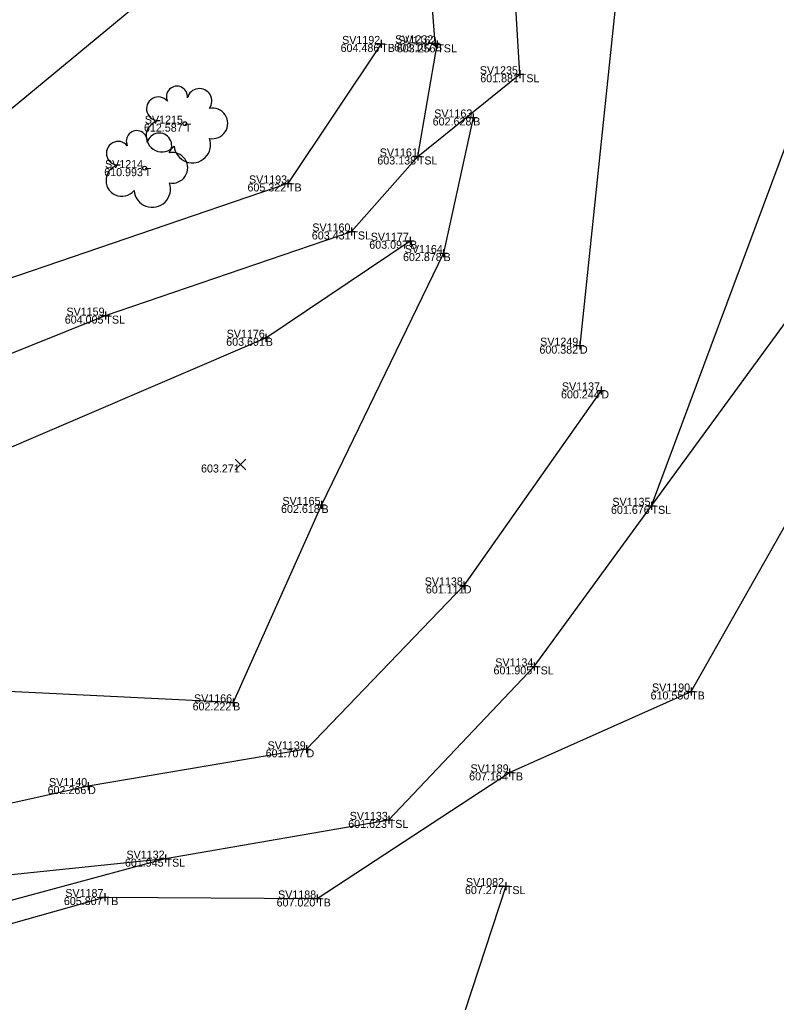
# Model space of a CAD drawing. Extents: x -2 to 1979875, y -2 to 232027.
# Drawn here: x 1978852.3 to 1978899.5, y 231261.4 to 231322.8 of the extents above; entities that cross this region are included whole.
import ezdxf

# ---------------------------------------------------------------- set-up
doc = ezdxf.new("R2010")
doc.units = 0
for name, color, linetype in [('_CIVIL_CONSTRUCTION', 7, 'Continuous'), ('DR_X_Ditch', 7, 'Continuous'), ('GE_P_Alignment', 7, 'Continuous'), ('GE_X_Alignment', 7, 'Continuous'), ('GE_X_Alignment_100_Curve_Data', 7, 'Continuous'), ('GE_X_Alignment_100_Stations', 7, 'Continuous'), ('HY_X_Water_Edge', 7, 'Continuous'), ('SV_X_Random_Point', 7, 'Continuous'), ('SV_X_Toe_of_Slope', 7, 'Continuous'), ('SV_X_Top_of_Bank', 7, 'Continuous'), ('VG_X_Cells', 7, 'Continuous')]:
    doc.layers.add(name, color=color, linetype=linetype)

msp = doc.modelspace()

# ---------------------------------------------------------------- linework, layer by layer
at = {"layer": 'DR_X_Ditch'}
for points in [[(1978869.602, 231440.78), (1978870, 231423.312), (1978870.757, 231401.498), (1978878.811, 231381.318), (1978885.453, 231363.805), (1978889.017, 231343.317), (1978889.726, 231326.131), (1978887.247, 231302.424)], [(1978888.584, 231299.627), (1978879.993, 231287.447), (1978870.172, 231277.213), (1978856.534, 231274.917), (1978839.012, 231271.025), (1978823.007, 231263.425), (1978802.617, 231258.705), (1978787.259, 231269.564)]]:
    msp.add_lwpolyline(points, dxfattribs=at)
at = {"layer": 'GE_P_Alignment'}
for points in [[(1978878.198, 231321.306), (1978876.972, 231337.361), (1978875.092, 231351.7)], [(1978823.841, 231302.538), (1978835.598, 231310.121), (1978846.229, 231312.385), (1978850.512, 231316.224), (1978859.326, 231323.503), (1978863.746, 231327.737), (1978864.641, 231332.322)], [(1978880.582, 231316.673), (1978878.73, 231308.205), (1978871.111, 231292.475), (1978865.586, 231280.144), (1978848.135, 231280.988), (1978836.093, 231277.946), (1978823.874, 231270.699), (1978811.412, 231263.896), (1978801.351, 231263.66), (1978797.393, 231268.655), (1978813.97, 231278.694), (1978829.592, 231287.989), (1978849.277, 231295.052), (1978867.627, 231302.914), (1978876.642, 231308.974)]]:
    msp.add_lwpolyline(points, dxfattribs=at)
at = {"layer": 'GE_X_Alignment_100_Curve_Data'}
for p, q in [((1978874.584, 231321.265), (1978875.084, 231321.265)), ((1978874.834, 231321.515), (1978874.834, 231321.015)), ((1978874.834, 231321.265), (1978874.834, 231321.265)), ((1978877.948, 231321.306), (1978878.448, 231321.306)), ((1978878.09, 231321.237), (1978878.59, 231321.237)), ((1978878.198, 231321.556), (1978878.198, 231321.056)), ((1978878.198, 231321.306), (1978878.198, 231321.306)), ((1978878.34, 231321.487), (1978878.34, 231320.987)), ((1978878.34, 231321.237), (1978878.34, 231321.237)), ((1978883.245, 231319.371), (1978883.745, 231319.371)), ((1978883.495, 231319.621), (1978883.495, 231319.121)), ((1978883.495, 231319.371), (1978883.495, 231319.371)), ((1978880.582, 231316.923), (1978880.582, 231316.423)), ((1978880.332, 231316.673), (1978880.832, 231316.673)), ((1978880.582, 231316.673), (1978880.582, 231316.673)), ((1978877.125, 231314.487), (1978877.125, 231313.987)), ((1978876.875, 231314.237), (1978877.375, 231314.237)), ((1978877.125, 231314.237), (1978877.125, 231314.237)), ((1978868.763, 231312.553), (1978869.263, 231312.553)), ((1978869.013, 231312.803), (1978869.013, 231312.303)), ((1978869.013, 231312.553), (1978869.013, 231312.553)), ((1978872.724, 231309.553), (1978873.224, 231309.553)), ((1978872.974, 231309.803), (1978872.974, 231309.303)), ((1978872.974, 231309.553), (1978872.974, 231309.553)), ((1978876.392, 231308.974), (1978876.892, 231308.974)), ((1978876.642, 231309.224), (1978876.642, 231308.724)), ((1978876.642, 231308.974), (1978876.642, 231308.974)), ((1978878.48, 231308.205), (1978878.98, 231308.205)), ((1978878.73, 231308.455), (1978878.73, 231307.955)), ((1978878.73, 231308.205), (1978878.73, 231308.205)), ((1978857.609, 231304.548), (1978857.609, 231304.048)), ((1978857.359, 231304.298), (1978857.859, 231304.298)), ((1978857.609, 231304.298), (1978857.609, 231304.298)), ((1978867.377, 231302.914), (1978867.877, 231302.914)), ((1978867.627, 231303.164), (1978867.627, 231302.664)), ((1978867.627, 231302.914), (1978867.627, 231302.914)), ((1978887.247, 231302.674), (1978887.247, 231302.174)), ((1978886.997, 231302.424), (1978887.497, 231302.424)), ((1978887.247, 231302.424), (1978887.247, 231302.424)), ((1978888.334, 231299.627), (1978888.834, 231299.627)), ((1978888.584, 231299.877), (1978888.584, 231299.377)), ((1978888.584, 231299.627), (1978888.584, 231299.627)), ((1978870.861, 231292.475), (1978871.361, 231292.475)), ((1978871.111, 231292.725), (1978871.111, 231292.225)), ((1978871.111, 231292.475), (1978871.111, 231292.475)), ((1978891.471, 231292.42), (1978891.971, 231292.42)), ((1978891.721, 231292.67), (1978891.721, 231292.17)), ((1978891.721, 231292.42), (1978891.721, 231292.42)), ((1978879.743, 231287.447), (1978880.243, 231287.447)), ((1978879.993, 231287.697), (1978879.993, 231287.197)), ((1978879.993, 231287.447), (1978879.993, 231287.447)), ((1978884.136, 231282.392), (1978884.636, 231282.392)), ((1978884.386, 231282.642), (1978884.386, 231282.142)), ((1978884.386, 231282.392), (1978884.386, 231282.392)), ((1978893.942, 231280.826), (1978894.442, 231280.826)), ((1978894.192, 231281.076), (1978894.192, 231280.576)), ((1978894.192, 231280.826), (1978894.192, 231280.826)), ((1978865.336, 231280.144), (1978865.836, 231280.144)), ((1978865.586, 231280.394), (1978865.586, 231279.894)), ((1978865.586, 231280.144), (1978865.586, 231280.144)), ((1978870.172, 231277.463), (1978870.172, 231276.963)), ((1978869.922, 231277.213), (1978870.422, 231277.213)), ((1978870.172, 231277.213), (1978870.172, 231277.213)), ((1978882.595, 231275.772), (1978883.095, 231275.772)), ((1978882.845, 231276.022), (1978882.845, 231275.522)), ((1978882.845, 231275.772), (1978882.845, 231275.772)), ((1978856.534, 231275.167), (1978856.534, 231274.667)), ((1978856.284, 231274.917), (1978856.784, 231274.917)), ((1978856.534, 231274.917), (1978856.534, 231274.917)), ((1978875.054, 231272.806), (1978875.554, 231272.806)), ((1978875.304, 231273.056), (1978875.304, 231272.556)), ((1978875.304, 231272.806), (1978875.304, 231272.806)), ((1978861.117, 231270.387), (1978861.617, 231270.387)), ((1978861.367, 231270.637), (1978861.367, 231270.137)), ((1978861.367, 231270.387), (1978861.367, 231270.387)), ((1978882.62, 231268.923), (1978882.62, 231268.423)), ((1978857.569, 231268.238), (1978857.569, 231267.738)), ((1978882.37, 231268.673), (1978882.87, 231268.673)), ((1978882.62, 231268.673), (1978882.62, 231268.673)), ((1978857.319, 231267.988), (1978857.819, 231267.988)), ((1978857.569, 231267.988), (1978857.569, 231267.988)), ((1978870.584, 231267.898), (1978871.084, 231267.898)), ((1978870.834, 231268.148), (1978870.834, 231267.648)), ((1978870.834, 231267.898), (1978870.834, 231267.898))]:
    msp.add_line(p, q, dxfattribs=at)
at = {"layer": 'HY_X_Water_Edge'}
for points in [[(1978738.528, 231278.008), (1978757.257, 231280.755), (1978763.371, 231281.556), (1978784.159, 231284.036), (1978793.351, 231279.988), (1978807.698, 231286.514), (1978821.562, 231291.295), (1978840.747, 231297.53), (1978857.609, 231304.298), (1978872.974, 231309.553), (1978877.125, 231314.237), (1978883.495, 231319.371), (1978882.175, 231341.325), (1978883.048, 231360.363), (1978875.551, 231375.847), (1978868.903, 231394.228), (1978864.235, 231416.891), (1978862.047, 231444.318), (1978861.234, 231465.995)], [(1978817.09, 231257.737), (1978832.082, 231262.479), (1978861.367, 231270.387), (1978875.304, 231272.806), (1978884.386, 231282.392), (1978891.721, 231292.42), (1978901.115, 231305.262)]]:
    msp.add_lwpolyline(points, dxfattribs=at)
at = {"layer": 'SV_X_Random_Point'}
for p, q in [((1978865.722, 231294.667), (1978866.388, 231295.335)), ((1978865.722, 231295.335), (1978866.388, 231294.667))]:
    msp.add_line(p, q, dxfattribs=at)
at = {"layer": 'SV_X_Toe_of_Slope'}
for points in [[(1978883.495, 231319.371), (1978882.175, 231341.325), (1978883.048, 231360.363), (1978875.551, 231375.847), (1978868.903, 231394.228), (1978864.235, 231416.891), (1978862.314, 231443.891)], [(1978783.289, 231254.287), (1978787.737, 231256.586), (1978799.967, 231256.811), (1978817.09, 231257.737), (1978832.082, 231262.479), (1978831.856, 231267.326), (1978861.367, 231270.387), (1978875.304, 231272.806), (1978884.386, 231282.392), (1978891.721, 231292.42), (1978902.966, 231322.566)], [(1978784.159, 231284.036), (1978793.351, 231279.988), (1978807.698, 231286.514), (1978821.562, 231291.295), (1978840.747, 231297.53), (1978857.609, 231304.298), (1978872.974, 231309.553), (1978877.125, 231314.237), (1978878.34, 231321.237)], [(1978882.62, 231268.673), (1978877.459, 231252.921), (1978870.251, 231232.89), (1978867.403, 231210.336), (1978862.637, 231194.058), (1978860.143, 231177.899), (1978861.272, 231163.63), (1978857.057, 231151.218), (1978852.299, 231137.119), (1978847.992, 231128.186), (1978840.449, 231114.42), (1978835.147, 231100.313)]]:
    msp.add_lwpolyline(points, dxfattribs=at)
at = {"layer": 'SV_X_Top_of_Bank'}
for points in [[(1978874.834, 231321.265), (1978869.013, 231312.553), (1978850.46, 231306.223), (1978834.564, 231301.781), (1978822.93, 231297.571), (1978810.304, 231294.189), (1978801.442, 231289.314), (1978795.097, 231290.638)], [(1978792.729, 231249.351), (1978802.059, 231250.56), (1978809.026, 231251.174), (1978824.702, 231257.152), (1978834.668, 231262.265), (1978843.76, 231264.082), (1978857.569, 231267.988), (1978870.834, 231267.898), (1978882.845, 231275.772), (1978894.192, 231280.826), (1978903.719, 231297.628)]]:
    msp.add_lwpolyline(points, dxfattribs=at)
at = {"layer": 'VG_X_Cells'}
for centre in [(1978862.57, 231316.285), (1978860.064, 231313.508)]:
    msp.add_circle(centre, 0.12, dxfattribs=at)
for centre, radius, start, end in [((1978862.078, 231317.969), 0.658, 354.0047, 205.97412), ((1978860.915, 231317.217), 0.735, 39.06254, 279.54124), ((1978863.483, 231317.7), 0.776, 323.82996, 165.0376), ((1978864.3, 231316.303), 0.957, 259.14531, 101.45961), ((1978861.143, 231315.511), 0.987, 96.17219, 320.57371), ((1978859.572, 231315.192), 0.658, 354.0047, 205.97412), ((1978860.977, 231314.923), 0.776, 323.82996, 165.0376), ((1978858.409, 231314.44), 0.735, 39.06254, 279.54124), ((1978863.043, 231314.982), 1.142, 184.94757, 19.45715), ((1978861.794, 231313.526), 0.957, 259.14531, 101.45961), ((1978858.637, 231312.734), 0.987, 96.17219, 320.57371), ((1978860.537, 231312.205), 1.142, 184.94757, 19.45715)]:
    msp.add_arc(centre, radius, start, end, dxfattribs=at)

# ---------------------------------------------------------------- texts
at = {"layer": '_CIVIL_CONSTRUCTION'}
for s, p in [('604.486', (1978872.302, 231320.765)), ('603.107', (1978875.647, 231320.806)), ('603.256', (1978875.808, 231320.737)), ('601.881', (1978881.025, 231318.871)), ('601.881', (1978881.025, 231318.871)), ('612.587', (1978860.019, 231315.785)), ('602.628', (1978878.052, 231316.173)), ('603.138', (1978874.595, 231313.737)), ('610.993', (1978857.539, 231313.008)), ('605.322', (1978866.485, 231312.053)), ('603.431', (1978870.504, 231309.053)), ('603.097', (1978874.091, 231308.474)), ('602.878', (1978876.2, 231307.705)), ('604.005', (1978855.074, 231303.798)), ('603.691', (1978865.157, 231302.414)), ('600.382', (1978884.719, 231301.924)), ('600.244', (1978886.068, 231299.127)), ('603.271', (1978863.585, 231294.501)), ('602.618', (1978868.581, 231291.975)), ('601.676', (1978889.189, 231291.92)), ('601.111', (1978877.626, 231286.947)), ('601.905', (1978881.851, 231281.892)), ('610.550', (1978891.662, 231280.326)), ('602.222', (1978863.058, 231279.644)), ('601.707', (1978867.621, 231276.713)), ('607.164', (1978880.329, 231275.272)), ('602.266', (1978854.002, 231274.417)), ('601.623', (1978872.779, 231272.306)), ('601.945', (1978858.832, 231269.887)), ('607.277', (1978880.069, 231268.173)), ('605.807', (1978855.018, 231267.488)), ('607.020', (1978868.304, 231267.398))]:
    msp.add_text(s, height=0.5, dxfattribs=at).set_placement(p)
at = {"layer": 'GE_X_Alignment'}
for s, p in [('SV1192', (1978872.396, 231321.265)), ('SV1232', (1978875.708, 231321.306)), ('SV1162', (1978875.902, 231321.237)), ('SV1235', (1978880.998, 231319.371)), ('SV1235', (1978880.998, 231319.371)), ('SV1215', (1978860.073, 231316.285)), ('SV1163', (1978878.148, 231316.673)), ('SV1161', (1978874.745, 231314.237)), ('SV1214', (1978857.587, 231313.508)), ('SV1193', (1978866.579, 231312.553)), ('SV1160', (1978870.534, 231309.553)), ('SV1177', (1978874.181, 231308.974)), ('SV1164', (1978876.305, 231308.205)), ('SV1159', (1978855.179, 231304.298)), ('SV1176', (1978865.185, 231302.914)), ('SV1249', (1978884.765, 231302.424)), ('SV1137', (1978886.123, 231299.627)), ('SV1165', (1978868.666, 231292.475)), ('SV1135', (1978889.276, 231292.42)), ('SV1138', (1978877.554, 231287.447)), ('SV1134', (1978881.961, 231282.392)), ('SV1190', (1978891.752, 231280.826)), ('SV1166', (1978863.144, 231280.144)), ('SV1139', (1978867.742, 231277.213)), ('SV1189', (1978880.415, 231275.772)), ('SV1140', (1978854.094, 231274.917)), ('SV1133', (1978872.87, 231272.806)), ('SV1132', (1978858.929, 231270.387)), ('SV1082', (1978880.13, 231268.673)), ('SV1187', (1978855.108, 231267.988)), ('SV1188', (1978868.395, 231267.898))]:
    msp.add_text(s, height=0.5, dxfattribs=at).set_placement(p)
at = {"layer": 'GE_X_Alignment_100_Stations'}
for s, p in [('TB', (1978874.834, 231320.765)), ('B', (1978878.198, 231320.806)), ('TSL', (1978878.34, 231320.737)), ('TSL', (1978883.495, 231318.871)), ('TSL', (1978883.495, 231318.871)), ('T', (1978862.57, 231315.785)), ('B', (1978880.582, 231316.173)), ('TSL', (1978877.125, 231313.737)), ('T', (1978860.064, 231313.008)), ('TB', (1978869.013, 231312.053)), ('TSL', (1978872.974, 231309.053)), ('B', (1978876.642, 231308.474)), ('B', (1978878.73, 231307.705)), ('TSL', (1978857.609, 231303.798)), ('B', (1978867.627, 231302.414)), ('D', (1978887.247, 231301.924)), ('D', (1978888.584, 231299.127)), ('B', (1978871.111, 231291.975)), ('TSL', (1978891.721, 231291.92)), ('D', (1978879.993, 231286.947)), ('TSL', (1978884.386, 231281.892)), ('TB', (1978894.192, 231280.326)), ('B', (1978865.586, 231279.644)), ('D', (1978870.172, 231276.713)), ('TB', (1978882.845, 231275.272)), ('D', (1978856.534, 231274.417)), ('TSL', (1978875.304, 231272.306)), ('TSL', (1978861.367, 231269.887)), ('TSL', (1978882.62, 231268.173)), ('TB', (1978857.569, 231267.488)), ('TB', (1978870.834, 231267.398))]:
    msp.add_text(s, height=0.5, dxfattribs=at).set_placement(p)

doc.saveas('drawing.dxf')
